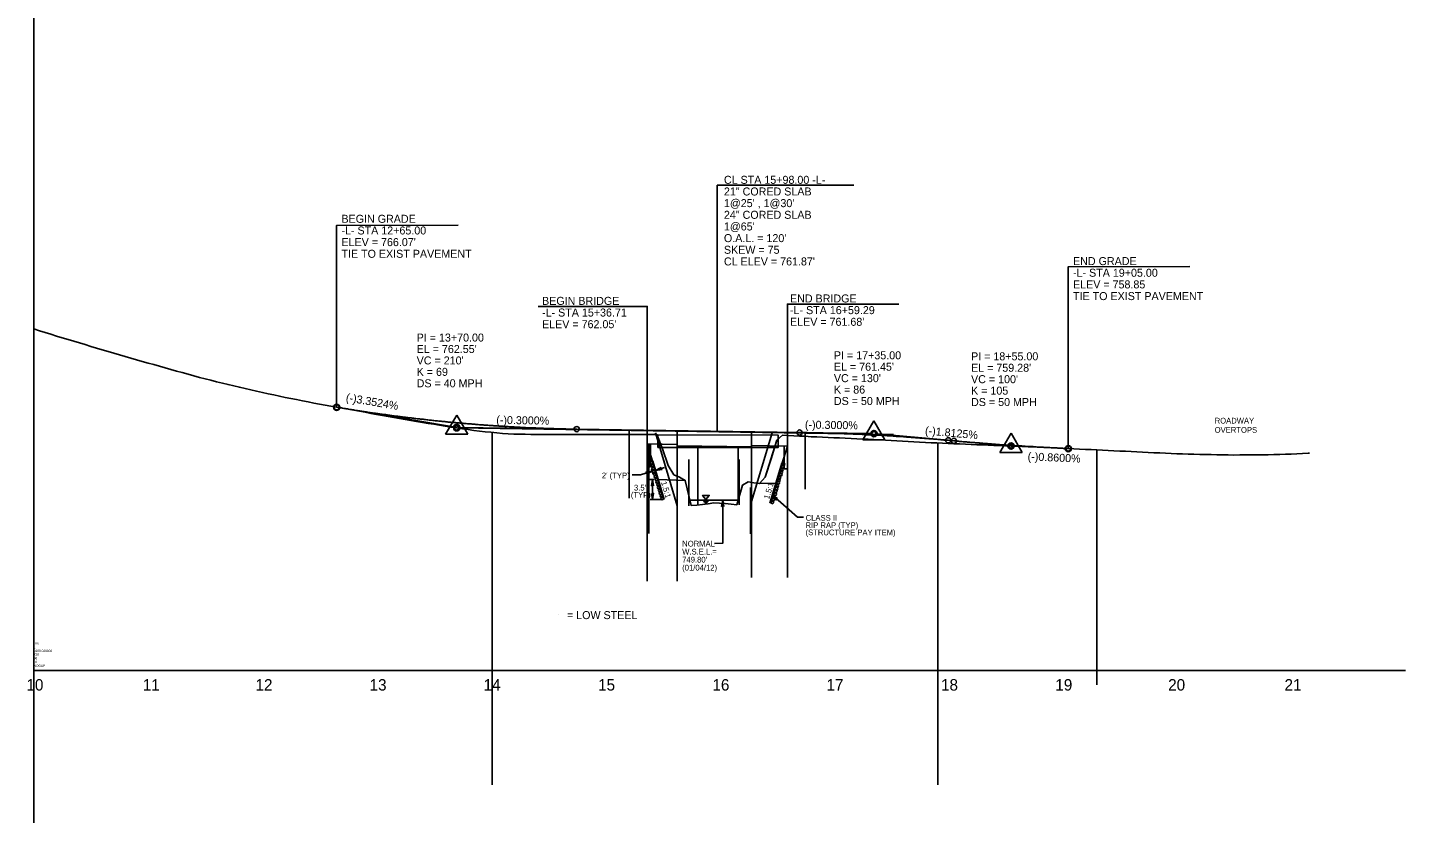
# Model space of a CAD drawing. Extents: x 1729958 to 1732200, y 880750 to 883250.
# Drawn here: x 1730995 to 1732200, y 881875 to 882562 of the extents above; entities that cross this region are included whole.
import ezdxf

# ---------------------------------------------------------------- set-up
doc = ezdxf.new("R2010")
doc.units = 0
for name, color, linetype in [('Exist Profile Cell', 7, 'Continuous'), ('Exist Structure Major Deck Tunnel Box Culvert', 7, 'Continuous'), ('Exist Vertical Profile Ground Line', 7, 'Continuous'), ('Exist Vertical Profile Horizontal Axis Label Major', 7, 'Continuous'), ('Level 11', 7, 'Continuous'), ('Level 7', 7, 'Continuous'), ('Level 8', 7, 'Continuous'), ('Prop DSN Text', 7, 'Continuous'), ('Prop PFL Text', 7, 'Continuous'), ('Prop PFL VPI Symbol CELL', 7, 'Continuous'), ('Prop Roadway Bridge', 7, 'Continuous'), ('Prop Vertical Profile Curve Label', 7, 'Continuous'), ('Prop Vertical Profile Grade', 7, 'Continuous'), ('Prop Vertical Profile Grade Label', 7, 'Continuous'), ('Prop VPI Label', 7, 'Continuous'), ('Scratch_Level_1', 7, 'Continuous'), ('Scratch_Level_2', 7, 'Continuous'), ('Scratch_Level_7', 7, 'Continuous')]:
    doc.layers.add(name, color=color, linetype=linetype)

msp = doc.modelspace()

# ---------------------------------------------------------------- linework, layer by layer
at = {"layer": 'Exist Profile Cell'}
for q in [(1731000, 883250), (1732200, 882000), (1731000, 880750)]:
    msp.add_line((1731000, 882000), q, dxfattribs=at)
at = {"layer": 'Exist Structure Major Deck Tunnel Box Culvert'}
for p, q in [((1731546.1, 882195.2), (1731546.1, 882206.3)), ((1731581.1, 882144.9), (1731581.1, 882195.2)), ((1731616.3, 882149.7), (1731616.3, 882195.2))]:
    msp.add_line(p, q, dxfattribs=at)
msp.add_lwpolyline([(1731546.1, 882206.3), (1731546.1, 882195.2), (1731651.3, 882195.2), (1731651.3, 882205.8)], close=True, dxfattribs=at)
at = {"layer": 'Exist Vertical Profile Ground Line'}
for points in [[(1731000, 882298.8), (1731005, 882297.3), (1731010, 882295.7), (1731015, 882294.2), (1731020, 882292.6), (1731025, 882291), (1731030, 882289.6), (1731035, 882288.1), (1731040, 882286.6), (1731045, 882285.1), (1731050, 882283.5), (1731055, 882282.1), (1731060, 882280.6), (1731065, 882279.2), (1731070, 882277.7), (1731075, 882276.2), (1731080, 882274.8), (1731085, 882273.3), (1731090, 882271.9), (1731095, 882270.5), (1731100, 882269), (1731105, 882267.6), (1731110, 882266.2), (1731115, 882264.8), (1731120, 882263.3), (1731125, 882262), (1731130, 882260.6), (1731135, 882259.2), (1731140, 882257.9), (1731145, 882256.5), (1731150, 882255.2), (1731155, 882254), (1731160, 882252.7), (1731165, 882251.4), (1731170, 882250.1), (1731175, 882249), (1731180, 882247.8), (1731185, 882246.7), (1731190, 882245.5), (1731195, 882244.4), (1731200, 882243.3), (1731205, 882242.2), (1731210, 882241.1), (1731215, 882240), (1731220, 882238.9), (1731225, 882237.9), (1731230, 882237), (1731235, 882236), (1731240, 882235), (1731245, 882234), (1731250, 882233.1), (1731255, 882232.2), (1731260, 882231.3), (1731265, 882230.4), (1731270, 882229.4), (1731275, 882228.6), (1731280, 882227.7), (1731285, 882226.8), (1731290, 882225.9), (1731295, 882224.9), (1731300, 882224.1), (1731305, 882223.2), (1731310, 882222.3), (1731315, 882221.4), (1731320, 882220.5), (1731325, 882219.6), (1731330, 882218.8), (1731335, 882217.9), (1731340, 882217.1), (1731345, 882216.2), (1731350, 882215.4), (1731355, 882214.6), (1731360, 882213.8), (1731365, 882212.9), (1731370, 882212.2), (1731375, 882211.5), (1731380, 882210.8), (1731385, 882210.1), (1731390, 882209.4), (1731395, 882208.9), (1731400, 882208.5), (1731405, 882208), (1731410, 882207.5), (1731415, 882207.1), (1731420, 882206.9), (1731425, 882206.8), (1731430, 882206.7), (1731435, 882206.5), (1731440, 882206.4), (1731445, 882206.4), (1731450, 882206.4), (1731455, 882206.5), (1731460, 882206.5), (1731465, 882206.5), (1731470, 882206.5), (1731475, 882206.5), (1731480, 882206.5), (1731485, 882206.6), (1731490, 882206.6), (1731495, 882206.5), (1731500, 882206.5)], [(1731500, 882206.5), (1731505, 882206.5), (1731510, 882206.5), (1731515, 882206.5), (1731520, 882206.4), (1731525, 882206.4), (1731530, 882206.4), (1731535, 882206.4), (1731540, 882206.4), (1731545, 882206.5), (1731550, 882193.9), (1731555, 882179.5), (1731560, 882171.3), (1731565, 882169.3), (1731570, 882166.4), (1731575, 882144.4), (1731580, 882144.8), (1731585, 882145.2), (1731590, 882145.9), (1731595, 882146.7), (1731600, 882146.5), (1731605, 882146), (1731610, 882145.5), (1731615, 882145.1), (1731620, 882162.3), (1731625, 882165.1), (1731630, 882164.3), (1731635, 882163.6), (1731640, 882169.2), (1731645, 882185.3), (1731650, 882201.4), (1731655, 882205.8), (1731660, 882205.6), (1731665, 882205.3), (1731670, 882205.1), (1731675, 882204.9), (1731680, 882204.6), (1731685, 882204.4), (1731690, 882204.2), (1731695, 882204), (1731700, 882203.7), (1731705, 882203.5), (1731710, 882203.3), (1731715, 882203), (1731720, 882202.8), (1731725, 882202.5), (1731730, 882202.3), (1731735, 882202.1), (1731740, 882201.8), (1731745, 882201.6), (1731750, 882201.3), (1731755, 882201), (1731760, 882200.7), (1731765, 882200.5), (1731770, 882200.2), (1731775, 882199.9), (1731780, 882199.6), (1731785, 882199.3), (1731790, 882199.1), (1731795, 882198.8), (1731800, 882198.6), (1731805, 882198.4), (1731810, 882198.2), (1731815, 882198), (1731820, 882197.8), (1731825, 882197.6), (1731830, 882197.4), (1731835, 882197.2), (1731840, 882197), (1731845, 882196.8), (1731850, 882196.6), (1731855, 882196.4), (1731860, 882196.2), (1731865, 882196), (1731870, 882195.8), (1731875, 882195.6), (1731880, 882195.4), (1731885, 882195.1), (1731890, 882194.9), (1731895, 882194.7), (1731900, 882194.5), (1731905, 882194.2), (1731910, 882194), (1731915, 882193.8), (1731920, 882193.5), (1731925, 882193.3), (1731930, 882193.1), (1731935, 882192.8), (1731940, 882192.6), (1731945, 882192.3), (1731950, 882192), (1731955, 882191.8), (1731960, 882191.5), (1731965, 882191.3), (1731970, 882191), (1731975, 882190.8), (1731980, 882190.6), (1731985, 882190.4), (1731990, 882190.1), (1731995, 882189.9), (1732000, 882189.7)], [(1732000, 882189.7), (1732005, 882189.6), (1732010, 882189.4), (1732015, 882189.3), (1732020, 882189.1), (1732025, 882189), (1732030, 882188.9), (1732035, 882188.8), (1732040, 882188.7), (1732045, 882188.6), (1732050, 882188.5), (1732055, 882188.6), (1732060, 882188.6), (1732065, 882188.6), (1732070, 882188.6), (1732075, 882188.7), (1732080, 882188.8), (1732085, 882188.9), (1732090, 882189.1), (1732095, 882189.2), (1732100, 882189.4), (1732105, 882189.7), (1732110, 882189.9), (1732115, 882190.2), (1732116, 882190.2)]]:
    msp.add_lwpolyline(points, dxfattribs=at)
at = {"layer": 'Level 11'}
for points in [[(1731570, 882166.4), (1731546.3, 882167), (1731536.7, 882198.2), (1731536.7, 882206.4), (1731545, 882206.5), (1731550, 882193.9), (1731555, 882179.5), (1731560, 882171.3), (1731565, 882169.3)], [(1731635, 882163.6), (1731649.3, 882164), (1731659.3, 882196.4), (1731659.3, 882205.6), (1731655, 882205.8), (1731650, 882201.4), (1731640, 882169.2)]]:
    msp.add_lwpolyline(points, close=True, dxfattribs=at)
at = {"layer": 'Level 7'}
for p, q in [((1731542.5, 882167), (1731539.1, 882167)), ((1731548.3, 882149.5), (1731539.3, 882149.5))]:
    msp.add_line(p, q, dxfattribs=at)
at = {"layer": 'Level 8'}
for p, q in [((1731616.1, 882149), (1731574, 882149)), ((1731590.5, 882148.6), (1731585.6, 882148.6)), ((1731589.8, 882147.6), (1731586.3, 882147.6)), ((1731589, 882146.7), (1731587, 882146.7))]:
    msp.add_line(p, q, dxfattribs=at)
msp.add_lwpolyline([(1731588, 882149.5), (1731590.9, 882153.2), (1731585.1, 882153.2)], close=True, dxfattribs=at)
at = {"layer": 'Prop DSN Text'}
for p, q in [((1731598, 882209.3), (1731598, 882424.5)), ((1731598, 882424.5), (1731717.3, 882424.5))]:
    msp.add_line(p, q, dxfattribs=at)
for points in [[(1731265, 882230.3), (1731265, 882389.4), (1731371.3, 882389.5)], [(1731905, 882194.2), (1731905, 882353.3), (1732011.3, 882353.4)], [(1731536.7, 882210.2), (1731536.7, 882318.6), (1731441.3, 882318.6)], [(1731659.3, 882208.4), (1731659.3, 882320.6), (1731756.7, 882320.6)], [(1731602.7, 882149), (1731602.7, 882111.3), (1731595.5, 882111.2)]]:
    msp.add_lwpolyline(points, dxfattribs=at)
for points in [[(1731536.2, 882171.8), (1731541.1, 882174.3), (1731535.6, 882173.6), (1731536.6, 882172.9)], [(1731548.9, 882177.6), (1731544, 882175.1), (1731549.5, 882175.8), (1731548.5, 882176.5)], [(1731603.6, 882143.6), (1731602.7, 882149), (1731601.7, 882143.6), (1731602.7, 882144.3)], [(1731650.8, 882150.6), (1731646.2, 882153.4), (1731649.6, 882149.1), (1731649.7, 882150.3)]]:
    msp.add_lwpolyline(points, close=True, dxfattribs=at)
at = {"layer": 'Prop PFL Text'}
for p, q in [((1731530.8, 882171.2), (1731523.6, 882171.2)), ((1731541.1, 882174.3), (1731530.8, 882171.2)), ((1731540.4, 882176.5), (1731541.9, 882171.7)), ((1731551.9, 882177.5), (1731544, 882175.1)), ((1731541.3, 882167), (1731541.3, 882149.5)), ((1731646.2, 882153.4), (1731668.3, 882134.1)), ((1731668.3, 882134.1), (1731673.3, 882134.1))]:
    msp.add_line(p, q, dxfattribs=at)
for points in [[(1731542.2, 882161.6), (1731541.3, 882167), (1731540.3, 882161.6), (1731541.3, 882162.3)], [(1731540.3, 882154.9), (1731541.3, 882149.5), (1731542.2, 882155), (1731541.3, 882154.3)]]:
    msp.add_lwpolyline(points, close=True, dxfattribs=at)
for centre in [(1731540.5, 882181.8), (1731541.2, 882179.4), (1731541.8, 882176.7), (1731542.5, 882174.3), (1731543.2, 882171.9), (1731543.9, 882169.6), (1731653.6, 882171.4), (1731654, 882173.6), (1731654.6, 882175.9), (1731655.3, 882178.1), (1731656.1, 882180.4), (1731544.6, 882167.2), (1731545.3, 882165), (1731546.1, 882162.6), (1731546.7, 882160.1), (1731547.6, 882157.6), (1731649.8, 882159.2), (1731650.5, 882161.6), (1731651.3, 882164.2), (1731652, 882166.6), (1731652.6, 882169), (1731548.3, 882155.2), (1731549, 882152.8), (1731549.7, 882150.4), (1731646.2, 882147.1), (1731646.9, 882149.5), (1731647.5, 882151.9), (1731648.6, 882154.3), (1731649.2, 882157)]:
    msp.add_circle(centre, 1.12, dxfattribs=at)
at = {"layer": 'Prop PFL VPI Symbol CELL'}
for p, q in [((1731370, 882223.5), (1731360.3, 882206.7)), ((1731370, 882223.5), (1731379.7, 882206.7)), ((1731735, 882218.5), (1731725.3, 882201.7)), ((1731735, 882218.5), (1731744.7, 882201.7)), ((1731855, 882207.6), (1731845.3, 882190.8)), ((1731855, 882207.6), (1731864.7, 882190.8)), ((1731360.3, 882206.7), (1731379.7, 882206.7)), ((1731725.3, 882201.7), (1731744.7, 882201.7)), ((1731845.3, 882190.8), (1731864.7, 882190.8))]:
    msp.add_line(p, q, dxfattribs=at)
for centre, radius in [((1731370, 882212.2), 2.62), ((1731370, 882212.2), 1.8), ((1731735, 882207.3), 2.62), ((1731735, 882207.3), 1.8), ((1731855, 882196.4), 2.62), ((1731855, 882196.4), 1.8)]:
    msp.add_circle(centre, radius, dxfattribs=at)
at = {"layer": 'Prop Roadway Bridge'}
for p, q in [((1731536.7, 882210.2), (1731536.7, 882198.2)), ((1731563, 882209.9), (1731563, 882197.8)), ((1731628, 882208.9), (1731628, 882196.8)), ((1731659.3, 882208.4), (1731659.3, 882196.4)), ((1731536.7, 882198.2), (1731563, 882197.8)), ((1731536.7, 882198.2), (1731536.7, 882178.2)), ((1731539.5, 882178.2), (1731539.5, 882198.2)), ((1731563, 882197.8), (1731563, 882196.6)), ((1731563, 882196.6), (1731628, 882195.6)), ((1731563, 882196.6), (1731563, 882078.1)), ((1731628, 882196.8), (1731659.3, 882196.4)), ((1731628, 882196.8), (1731628, 882195.6)), ((1731628, 882195.6), (1731628, 882081.4)), ((1731656.6, 882176.4), (1731656.6, 882196.4)), ((1731659.3, 882196.4), (1731659.3, 882176.4)), ((1731539.5, 882183.2), (1731541.5, 882183.2)), ((1731541.5, 882183.2), (1731551.6, 882149.5)), ((1731536.7, 882178.2), (1731539.5, 882178.2)), ((1731536.7, 882178.2), (1731536.7, 882078.1)), ((1731654.6, 882181.5), (1731644.1, 882146.4)), ((1731654.6, 882181.5), (1731656.6, 882181.5)), ((1731659.3, 882176.4), (1731656.6, 882176.4)), ((1731659.3, 882176.4), (1731659.3, 882081.4)), ((1731546.3, 882167), (1731570, 882166.4)), ((1731649.3, 882164), (1731635, 882163.6))]:
    msp.add_line(p, q, dxfattribs=at)
at = {"layer": 'Prop Vertical Profile Curve Label'}
for centre in [(1731265, 882230.3), (1731905, 882194.2)]:
    msp.add_circle(centre, 2.25, dxfattribs=at)
at = {"layer": 'Prop Vertical Profile Grade'}
for p, q in [((1731475, 882211.2), (1731670, 882208.2)), ((1731800, 882201.4), (1731805, 882200.9))]:
    msp.add_line(p, q, dxfattribs=at)
for points in [[(1731265, 882230.3), (1731269.2, 882229.7), (1731273.4, 882229), (1731277.6, 882228.3), (1731281.8, 882227.6), (1731286, 882227), (1731290.2, 882226.4), (1731294.4, 882225.7), (1731298.6, 882225.1), (1731302.8, 882224.5), (1731307, 882224), (1731311.2, 882223.4), (1731315.4, 882222.8), (1731319.6, 882222.3), (1731323.8, 882221.8), (1731328, 882221.2), (1731332.2, 882220.7), (1731336.4, 882220.2), (1731340.6, 882219.8), (1731344.8, 882219.3), (1731349, 882218.8), (1731353.2, 882218.4), (1731357.4, 882218), (1731361.6, 882217.5), (1731365.8, 882217.1), (1731370, 882216.8), (1731374.2, 882216.4), (1731378.4, 882216), (1731382.6, 882215.7), (1731386.8, 882215.3), (1731391, 882215), (1731395.2, 882214.7), (1731399.4, 882214.4), (1731403.6, 882214.1), (1731407.8, 882213.8), (1731412, 882213.6), (1731416.2, 882213.3), (1731420.4, 882213.1), (1731424.6, 882212.9), (1731428.8, 882212.6), (1731433, 882212.4), (1731437.2, 882212.3), (1731441.4, 882212.1), (1731445.6, 882211.9), (1731449.8, 882211.8), (1731454, 882211.7), (1731458.2, 882211.5), (1731462.4, 882211.4), (1731466.6, 882211.3), (1731470.8, 882211.2), (1731475, 882211.2)], [(1731670, 882208.2), (1731672.6, 882208.2), (1731675.2, 882208.2), (1731677.8, 882208.1), (1731680.4, 882208.1), (1731683, 882208), (1731685.6, 882207.9), (1731688.2, 882207.9), (1731690.8, 882207.8), (1731693.4, 882207.7), (1731696, 882207.7), (1731698.6, 882207.6), (1731701.2, 882207.5), (1731703.8, 882207.4), (1731706.4, 882207.3), (1731709, 882207.2), (1731711.6, 882207.1), (1731714.2, 882207), (1731716.8, 882206.9), (1731719.4, 882206.8), (1731722, 882206.7), (1731724.6, 882206.6), (1731727.2, 882206.4), (1731729.8, 882206.3), (1731732.4, 882206.2), (1731735, 882206), (1731737.6, 882205.9), (1731740.2, 882205.8), (1731742.8, 882205.6), (1731745.4, 882205.5), (1731748, 882205.3), (1731750.6, 882205.2), (1731753.2, 882205), (1731755.8, 882204.8), (1731758.4, 882204.7), (1731761, 882204.5), (1731763.6, 882204.3), (1731766.2, 882204.1), (1731768.8, 882203.9), (1731771.4, 882203.7), (1731774, 882203.5), (1731776.6, 882203.3), (1731779.2, 882203.1), (1731781.8, 882202.9), (1731784.4, 882202.7), (1731787, 882202.5), (1731789.6, 882202.3), (1731792.2, 882202.1), (1731794.8, 882201.8), (1731797.4, 882201.6), (1731800, 882201.4)], [(1731805, 882200.9), (1731807, 882200.8), (1731809, 882200.6), (1731811, 882200.4), (1731813, 882200.2), (1731815, 882200), (1731817, 882199.9), (1731819, 882199.7), (1731821, 882199.5), (1731823, 882199.4), (1731825, 882199.2), (1731827, 882199.1), (1731829, 882198.9), (1731831, 882198.7), (1731833, 882198.6), (1731835, 882198.4), (1731837, 882198.3), (1731839, 882198.1), (1731841, 882198), (1731843, 882197.8), (1731845, 882197.7), (1731847, 882197.5), (1731849, 882197.4), (1731851, 882197.3), (1731853, 882197.1), (1731855, 882197), (1731857, 882196.9), (1731859, 882196.7), (1731861, 882196.6), (1731863, 882196.5), (1731865, 882196.4), (1731867, 882196.2), (1731869, 882196.1), (1731871, 882196), (1731873, 882195.9), (1731875, 882195.8), (1731877, 882195.6), (1731879, 882195.5), (1731881, 882195.4), (1731883, 882195.3), (1731885, 882195.2), (1731887, 882195.1), (1731889, 882195), (1731891, 882194.9), (1731893, 882194.8), (1731895, 882194.7), (1731897, 882194.6), (1731899, 882194.5), (1731901, 882194.4), (1731903, 882194.3), (1731905, 882194.2)]]:
    msp.add_spline(points, degree=3, dxfattribs=at)
at = {"layer": 'Prop VPI Label'}
for p, q in [((1731265, 882230.3), (1731367.3, 882213.2)), ((1731475, 882211.2), (1731372.7, 882212.7)), ((1731670, 882208.2), (1731732.3, 882207.3)), ((1731800, 882201.4), (1731737.7, 882207)), ((1731805, 882200.9), (1731852.3, 882196.6)), ((1731905, 882194.2), (1731857.7, 882196.3))]:
    msp.add_line(p, q, dxfattribs=at)
for centre, radius in [((1731265, 882230.3), 2.75), ((1731370, 882212.8), 2.75), ((1731475, 882211.2), 2.25), ((1731670, 882208.2), 2.25), ((1731735, 882207.3), 2.75), ((1731800, 882201.4), 2.25), ((1731805, 882200.9), 2.25), ((1731855, 882196.4), 2.75), ((1731905, 882194.2), 2.75)]:
    msp.add_circle(centre, radius, dxfattribs=at)
at = {"layer": 'Scratch_Level_1'}
for p, q in [((1731369.9, 882212.2), (1731752.1, 882206.5)), ((1731401, 881900), (1731401, 882208.4)), ((1731521, 882209.9), (1731521, 882150.8)), ((1731675, 882207.6), (1731675, 882158.7)), ((1731538, 882198.5), (1731538, 882119.8)), ((1731791, 881900), (1731791, 882199)), ((1731930, 881987.5), (1731930, 882193.1))]:
    msp.add_line(p, q, dxfattribs=at)
at = {"layer": 'Scratch_Level_2'}
for p, q in [((1731563, 882144.2), (1731543.9, 882208)), ((1731627, 882145), (1731645.9, 882208)), ((1731573, 882144.2), (1731573, 882184.5)), ((1731617, 882145), (1731617, 882184.5)), ((1731563, 882119.6), (1731563, 882160.2)), ((1731627, 882119.6), (1731627, 882160.2))]:
    msp.add_line(p, q, dxfattribs=at)
at = {"layer": 'Scratch_Level_7'}
for p, q in [((1731651, 882208), (1731651, 882208)), ((1731459.4, 882048.6), (1731459.4, 882048.6))]:
    msp.add_line(p, q, dxfattribs=at)

# ---------------------------------------------------------------- texts
at = {"layer": 'Exist Profile Cell'}
for s, p in [('720', (1731000, 882013)), ('100', (1731000, 882022.8)), ('L', (1731000, 882019.5)), ('1000.000000', (1731000, 882016.2)), ('50', (1731000, 882009.8)), ('10', (1731000, 882006.5)), ('NOGAP', (1731000, 882003.2))]:
    msp.add_text(s, height=2, dxfattribs=at).set_placement(p)
at = {"layer": 'Exist Vertical Profile Horizontal Axis Label Major'}
for s, p in [('10', (1730993.6, 881982.5)), ('11', (1731095.4, 881982.5)), ('12', (1731194, 881982.5)), ('13', (1731293.8, 881982.5)), ('14', (1731393.6, 881982.5)), ('15', (1731493.7, 881982.5)), ('16', (1731593.7, 881982.5)), ('17', (1731693.5, 881982.5)), ('18', (1731793.7, 881982.5)), ('19', (1731893.7, 881982.5)), ('20', (1731992.4, 881982.5)), ('21', (1732094.2, 881982.5))]:
    msp.add_text(s, height=10, dxfattribs=at).set_placement(p)
at = {"layer": 'Prop DSN Text'}
for s, height, p in [('CL STA 15+98.00 -L-', 7, (1731603.8, 882425.8)), ('21" CORED SLAB', 7, (1731603.8, 882415.6)), ("1@25' , 1@30'", 7, (1731603.8, 882405.4)), ('24" CORED SLAB', 7, (1731603.8, 882395.2)), ('-L- STA 12+65.00 ', 7, (1731269.2, 882381.5)), ('BEGIN GRADE', 7, (1731269.2, 882391.7)), ("1@65'", 7, (1731603.8, 882385)), ("ELEV = 766.07'", 7, (1731269.2, 882371.3)), ("O.A.L. = 120'", 7, (1731603.8, 882374.8)), ('TIE TO EXIST PAVEMENT', 7, (1731269.2, 882361.1)), ('SKEW = 75', 7, (1731603.8, 882364.6)), ("CL ELEV = 761.87'", 7, (1731603.8, 882354.4)), ('-L- STA 19+05.00 ', 7, (1731909.2, 882344.5)), ('END GRADE', 7, (1731909.2, 882354.7)), ('ELEV = 758.85', 7, (1731909.2, 882334.3)), ('END BRIDGE', 7, (1731661.6, 882322)), ('TIE TO EXIST PAVEMENT', 7, (1731909.2, 882324.1)), ('-L- STA 15+36.71', 7, (1731444.7, 882309.7)), ('BEGIN BRIDGE ', 7, (1731444.7, 882319.9)), ('-L- STA 16+59.29', 7, (1731661.6, 882311.8)), ("ELEV = 762.05'", 7, (1731444.7, 882299.5)), ("ELEV = 761.68'", 7, (1731661.6, 882301.6)), ('DS = 40 MPH', 7, (1731335, 882247.8)), ('DS = 50 MPH', 7, (1731700, 882232.3)), ('DS = 50 MPH', 7, (1731820, 882231.4)), ('NORMAL   ', 5, (1731567.3, 882108.5)), ('W.S.E.L.= ', 5, (1731567.3, 882101.5)), ("749.80'", 5, (1731567.3, 882094.5)), ('(01/04/12)', 5, (1731567.3, 882087.5))]:
    msp.add_text(s, height=height, dxfattribs=at).set_placement(p)
for s, rotation, p in [("2' (TYP)", 359.9189, (1731497, 882168.2)), ("3.5'", 359.9189, (1731525.1, 882157.5)), ('1.5:1', 286.6992, (1731548.7, 882164.7)), ('1.5:1', 73.8893, (1731643.3, 882149.5)), ('(TYP)', 359.9189, (1731522.4, 882151.2))]:
    msp.add_text(s, height=5, rotation=rotation, dxfattribs=at).set_placement(p)
at = {"layer": 'Prop PFL Text'}
for s, p in [('CLASS II ', (1731675.3, 882131.1)), ('(STRUCTURE PAY ITEM)', (1731675.2, 882118.4)), ('RIP RAP (TYP)', (1731675.2, 882124.7))]:
    msp.add_text(s, height=5, rotation=359.9189, dxfattribs=at).set_placement(p)
at = {"layer": 'Prop Vertical Profile Curve Label'}
for s, p in [('PI = 13+70.00', (1731335, 882287.8)), ("EL = 762.55'", (1731335, 882277.8)), ('PI = 17+35.00', (1731700, 882272.3)), ("VC = 210'", (1731335, 882267.8)), ("EL = 761.45'", (1731700, 882262.3)), ('PI = 18+55.00', (1731820, 882271.4)), ("EL = 759.28'", (1731820, 882261.4)), ('K = 69', (1731335, 882257.8)), ("VC = 130'", (1731700, 882252.3)), ("VC = 100'", (1731820, 882251.4)), ('K = 86', (1731700, 882242.3)), ('K = 105', (1731820, 882241.4))]:
    msp.add_text(s, height=7, dxfattribs=at).set_placement(p)
at = {"layer": 'Prop Vertical Profile Grade Label'}
for s, rotation, p in [('(-)3.3524%', 350.4846, (1731272.7, 882235.6)), ('(-)0.3000%', 359.1406, (1731404.6, 882215.8)), ('(-)0.3000%', 359.1406, (1731674.6, 882211.7)), ('(-)1.8125%', 354.8217, (1731779.5, 882206.6)), ('(-)0.8600%', 357.5378, (1731869.4, 882183.9))]:
    msp.add_text(s, height=7, rotation=rotation, dxfattribs=at).set_placement(p)
at = {"layer": 'Scratch_Level_1'}
for s, p in [('ROADWAY', (1732033.1, 882216.1)), ('OVERTOPS', (1732033.1, 882208))]:
    msp.add_text(s, height=5, dxfattribs=at).set_placement(p)
at = {"layer": 'Scratch_Level_7'}
msp.add_text('= LOW STEEL', height=7, dxfattribs=at).set_placement((1731466.5, 882045))

doc.saveas('drawing.dxf')
